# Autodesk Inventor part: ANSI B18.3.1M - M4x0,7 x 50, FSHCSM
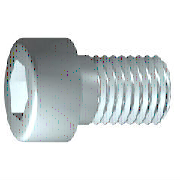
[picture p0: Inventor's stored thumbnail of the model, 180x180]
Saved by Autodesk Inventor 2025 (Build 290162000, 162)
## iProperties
Created: 2024-01
Part Number: ANSI B18.3.1M - M4x0,7 x 50, FSHCSM
Material: Acciaio, Dolce
Description: Vite forgiata a testa incassata - Metrico
Document SubType Name: Modeling
Standard: ANSI B18.3.1M
Designer: Ryzen5700u
Standard Revision: 1979
Standards Organization: ANSI
Language: it-IT
Size Designation: M4x0,7 x 50
Categories: <MemberInstance><Categories><Category DisplayName="Elementi di fissaggio" InternalName="e4da775c-781d-43d5-af7c-5136215cf5a6" Mnemonic="FSTN"><Category DisplayN
Density: 7.85 g/cm^3
Appearance: Semilucidato
IsCustomPart: 0
Author: Ryzen5700u
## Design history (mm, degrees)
body "Solid1"
workplane "Work Plane1"
fillet "Fillet2" dims "d30" = 0.1 (= R)
revolve "Corpo" stored, may be unused: angle "d10" = 90 deg
sketch "Schizzo2"
  geometry: L1 (0, -4.9)-(0, 4.9) reference; L2 (-4.9, 0)-(4.9, 0) reference; L3 (1.732, 0)-(0.866, -1.5); L4 (0.866, -1.5)-(-0.866, -1.5); L5 (-0.866, -1.5)-(-1.732, 0); L6 (-1.732, 0)-(-0.866, 1.5); L7 (-0.866, 1.5)-(0.866, 1.5); L8 (0.866, 1.5)-(1.732, 0); 2 further points
  constraints: 12 end point, 1 coincident, 1 horizontal alignment, 1 point on line, 12 other
extrude "Intaglio" join sketch "Schizzo2" stored distance "d11" = 10; taper "d12" = 0 deg
fillet "Raccordo1" dims "d17" = 0.4 (= RR)
feature "Filettatura" dims "d13" = 20 (= GEL), "d14" = 0
chamfer "Smusso1" distance "d15" = 0.42942 (= -0.5 x SPD + 0.5 x GD); stored, may be unused: second distance "d16" = 0.42941 (= GUL), angle "d27" = 45 deg
sketch "Schizzo1"
  geometry: L1 (-1, 0)-(50, 0); L2 (50, 0)-(50, 2); L3 (50, 2)-(30, 2); L4 (30, 2)-(29.57, 2); L5 (29.57, 2)-(0, 2); L6 (0, 2)-(0, 3.5); L7 (0, 3.5)-(-4, 3.5); L8 (-4, 3.5)-(-4, 1.732); L9 (-4, 1.732)-(-2, 1.732); L10 (-2, 1.732)-(-1, 0); L11 (-14.8, 0)-(60.8, 0) reference; L12 (0, -0.7)-(0, 4.2) reference; L13 (30, 2)-(0, 2)
  constraints: 22 end point, 6 parallel, 2 collinear, 2 perpendicular, 1 horizontal, 1 point on line
  dimensions: "d1" = 20 distance from line of L3.end L2 (= GEL); "d2" = 0.42952 distance of L4.end L3.end (computed from GAL); "d3" = 4 distance between parallel lines of L8 L6 (= KOH); "d4" = 2 distance of L8.end L9.end (= INTI); "d5" = 60 deg angle of L10 L1; "d6" = 4 diameter of L3 L1 (= GD); "d7" = 4 diameter of L5 L1 (= BDM); "d8" = 3.4641 diameter of L9 L1 (= 1.1547 x SW); "d9" = 7 diameter of L7 L1 (= KOD); "d26" = 50 distance between parallel lines of L12 L2 (= NLG)
other parameters: "GD" = 4 (= NND) [user parameter; used in 2 equation terms], "NLG" = 50 [user parameter; used in 1 equation term], "GEL" = 20 [user parameter; used in 2 equation terms], "KOD" = 7 [user parameter; used in 1 equation term], "KOH" = 4 [user parameter; used in 1 equation term], "INTI" = 2 [user parameter; used in 1 equation term], "GAL" = 0.42941 (= 0.61345 x PTC) [user parameter; used in 1 equation term], "GUL" = 0.42941 (= 0.61345 x PTC) [user parameter; used in 1 equation term], "BDM" = 4 (= NND) [user parameter; used in 1 equation term], "SW" = 3 [user parameter; used in 2 equation terms], "RR" = 0.4 [user parameter; used in 1 equation term], "SPD" = 3.14117 [user parameter; used in 1 equation term], "d19" = 0, "d28" = 0, "d29" = 0, "R" = 0.1 [user parameter; used in 1 equation term], "TOA" = 30 deg [user parameter], "THREADDIA" = 4 [user parameter; used in 1 equation term], "TPU" = 14.28571 (computed from PTC) [user parameter], "PTC" = 0.7 [user parameter; used in 4 equation terms], "NND" = 4 [user parameter; used in 2 equation terms], "E0" = 3.465 (= 1.155 x SW) [user parameter], "GD1" = 3.14117 (= THREADDIA - 1.2269 x PTC) [user parameter]
